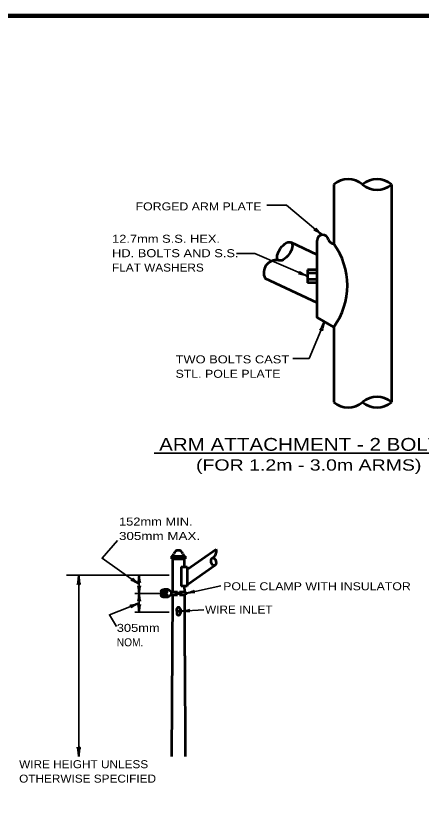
# Model space of a CAD drawing. Extents: x -23 to 690, y -228 to 443.
# Drawn here: x 229.5 to 356, y 192.8 to 437.8 of the extents above; entities that cross this region are included whole.
import ezdxf
from ezdxf.enums import TextEntityAlignment as Align

# ---------------------------------------------------------------- set-up
doc = ezdxf.new("R2010")
doc.units = 0
doc.layers.add('1', color=7, linetype='Continuous', lineweight=35)

msp = doc.modelspace()

# ---------------------------------------------------------------- hatches: boundary and pattern name
at = {"layer": '1'}
h = msp.add_hatch(color=256, dxfattribs=at)
edge = h.paths.add_edge_path()
edge.add_ellipse((275.808, 258.088), major_axis=(0.907, 0), ratio=0.6666667, start_angle=0, end_angle=360)
h = msp.add_hatch(color=256, dxfattribs=at)
edge = h.paths.add_edge_path()
edge.add_ellipse((275.808, 256.835), major_axis=(0.907, 0), ratio=0.6666667, start_angle=0, end_angle=360)

# ---------------------------------------------------------------- linework, layer by layer
at = {"layer": '1', "lineweight": 53}
for p, q in [((328.678, 385.1), (328.678, 366.6)), ((346.678, 385.1), (346.678, 317.1)), ((323.561, 363.183), (315.404, 366.986)), ((323.482, 358.445), (320.482, 358.445)), ((320.482, 358.445), (320.482, 354.445)), ((323.561, 348.183), (307.247, 355.79)), ((323.482, 357.445), (320.482, 357.445)), ((323.482, 355.445), (320.482, 355.445)), ((323.482, 354.445), (320.482, 354.445)), ((328.678, 340.6), (328.678, 317.1)), ((283.035, 265.061), (291.955, 271.301)), ((278.1, 269.095), (282.32, 269.095)), ((278.1, 269.095), (278.1, 268.195)), ((278.1, 268.195), (282.32, 268.195)), ((278.4, 268.195), (278.34, 257.915)), ((282.02, 268.195), (282.04, 265.775)), ((282.32, 269.095), (282.32, 268.195)), ((281.11, 265.775), (283.01, 265.775)), ((281.11, 265.775), (281.11, 259.735)), ((283.01, 265.775), (283.01, 259.735)), ((283.035, 260.221), (291.475, 266.121)), ((283.01, 259.735), (281.11, 259.735)), ((282.06, 259.735), (282.08, 257.915)), ((277.02, 258.695), (275.8, 258.695)), ((277.94, 257.915), (277.02, 258.695)), ((277.94, 257.915), (279.92, 257.915)), ((277.94, 257.915), (277.94, 257.015)), ((279.42, 257.915), (279.42, 257.015)), ((279.92, 257.915), (279.92, 257.015)), ((280.52, 257.915), (282.48, 257.915)), ((280.52, 257.915), (280.52, 257.015)), ((281, 257.915), (281, 257.015)), ((282.48, 257.915), (282.48, 257.015)), ((277.02, 256.235), (275.8, 256.235)), ((277.94, 257.015), (277.02, 256.235)), ((277.94, 257.015), (279.92, 257.015)), ((278.34, 257.015), (278.1, 206.515)), ((280.52, 257.015), (282.48, 257.015)), ((282.08, 257.015), (282.168, 237.955)), ((279.68, 252.455), (279.7, 251.255)), ((280.9, 252.475), (280.9, 251.255)), ((282.18, 237.955), (282.32, 206.515))]:
    msp.add_line(p, q, dxfattribs=at)
at = {"layer": '1'}
for p, q in [((272.629, 301.175), (367.649, 301.175)), ((245.329, 263.089), (277.329, 263.089)), ((249.145, 263.089), (249.145, 206.515)), ((267.971, 257.404), (267.971, 263.089)), ((282.509, 257.449), (293.413, 259.808)), ((266.657, 257.404), (274.657, 257.404)), ((267.971, 257.404), (267.971, 251.593)), ((280.94, 251.88), (288.21, 252.352)), ((266.657, 251.593), (277.329, 251.593))]:
    msp.add_line(p, q, dxfattribs=at)
at = {"layer": '1', "lineweight": 158}
msp.add_lwpolyline([(684.026, 437.805), (24.276, 437.722), (24.36, -0.611)], dxfattribs=at)
at = {"layer": '1'}
for points in [[(325.01, 369.374), (313.992, 378.629), (307.832, 378.629)], [(320.482, 356.445), (304.054, 363.511), (298.304, 363.511)], [(325.826, 342.247), (320.974, 330.729), (315.963, 330.729)], [(268.019, 260.256), (256.395, 268.416), (261.221, 273.923)], [(267.951, 254.408), (258.706, 250.804), (260.882, 247.133)]]:
    msp.add_lwpolyline(points, dxfattribs=at)
at = {"layer": '1', "lineweight": 53}
msp.add_lwpolyline([(328.678, 340.6), (323.482, 343.6), (323.482, 367.6)], dxfattribs=at)
for centre, radius, start, end in [((333.178, 379.861), 6.907, 49.34186, 130.65814), ((342.178, 379.861), 6.907, 49.34186, 130.65814), ((342.178, 390.332), 6.907, 229.34186, 310.65814), ((325.269, 367.606), 1.787, 7.93348, 180.19616), ((328.793, 368.449), 1.852, 198.77174, 266.46102), ((310.949, 353.6), 21.985, 323.74899, 36.25101), ((310.874, 357.511), 4.015, 82.46091, 205.39139), ((342.178, 311.869), 6.907, 49.34186, 130.65814), ((333.178, 322.34), 6.907, 229.34186, 310.65814), ((342.178, 322.34), 6.907, 229.34186, 310.65814), ((277.902, 270.019), 0.936, 281.94387, 347.91984), ((280.213, 269.418), 1.453, 16.19781, 163.80219), ((282.523, 270.019), 0.936, 192.08016, 258.05613), ((289.835, 270.525), 2.264, 295.32486, 20.09191), ((280.289, 252.478), 0.605, 358.85054, 181.71286), ((280.295, 251.269), 0.605, 358.85054, 181.71286), ((280.295, 251.232), 0.605, 178.28714, 1.14946)]:
    msp.add_arc(centre, radius, start, end, dxfattribs=at)
at = {"layer": '1', "lineweight": 40}
for centre, major_axis, ratio, start_param, end_param in [((323.997, 369.865), (1.468, -1.029), 0.122415, 0.8963533, 3.1415927), ((323.997, 369.865), (1.468, -1.029), 0.122415, 0.8963533, 3.1415927), ((324.288, 370.257), (-1.232, 1.264), 0.07063, 6.2823074, 8.5597026), ((324.288, 370.257), (-1.232, 1.264), 0.07063, 6.2823074, 8.5597026), ((319.536, 357.082), (1.544, -0.855), 0.07063, 3.1407148, 5.41811), ((319.536, 357.082), (1.544, -0.855), 0.07063, 3.1407148, 5.41811), ((319.371, 356.622), (1.702, -0.562), 0.122415, 0.8963533, 3.1415927), ((319.371, 356.622), (1.702, -0.562), 0.122415, 0.8963533, 3.1415927), ((325.196, 341.297), (-0.844, -1.55), 0.07063, 6.2823074, 8.5597026), ((325.196, 341.297), (-0.844, -1.55), 0.07063, 6.2823074, 8.5597026), ((325.657, 341.134), (0.549, 1.706), 0.122415, 0.8963533, 3.1415927), ((325.657, 341.134), (0.549, 1.706), 0.122415, 0.8963533, 3.1415927), ((248.933, 261.968), (0.176, 1.756), 0.07063, 3.1407148, 5.41811), ((249.421, 261.998), (-0.156, 1.786), 0.122415, 0.8963533, 3.1415927), ((267.223, 261.073), (-1.337, 1.153), 0.07063, 6.2823074, 8.5597026), ((267.223, 261.073), (-1.337, 1.153), 0.07063, 6.2823074, 8.5597026), ((267.763, 261.959), (0.176, 1.756), 0.07063, 4.6265008, 5.41811), ((268.251, 261.989), (-0.156, 1.786), 0.122415, 0.8963533, 1.6612166), ((266.967, 260.657), (1.551, -0.898), 0.122415, 0.8963533, 3.1415927), ((266.967, 260.657), (1.551, -0.898), 0.122415, 0.8963533, 3.1415927), ((267.82, 262.451), (0.176, 1.756), 0.07063, 3.1407148, 4.3375003), ((267.82, 258.043), (0.176, -1.756), 0.07063, 1.9456851, 3.1424706), ((268.191, 262.498), (-0.156, 1.786), 0.122415, 1.9568509, 3.1415927), ((268.191, 257.995), (-0.156, -1.786), 0.122415, 3.1415927, 4.3263344), ((267.763, 258.534), (0.176, -1.756), 0.07063, 0.8650754, 1.6566845), ((267.763, 256.275), (0.176, 1.756), 0.07063, 4.6265008, 5.41811), ((268.251, 258.505), (-0.156, -1.786), 0.122415, 4.6219687, 5.386832), ((268.251, 256.304), (-0.156, 1.786), 0.122415, 0.8963533, 1.6612166), ((283.517, 257.95), (-1.712, -0.53), 0.122415, 0.8963533, 3.1415927), ((283.517, 257.95), (-1.712, -0.53), 0.122415, 0.8963533, 3.1415927), ((283.649, 257.479), (1.754, 0.2), 0.07063, 6.2823074, 8.5597026), ((283.649, 257.479), (1.754, 0.2), 0.07063, 6.2823074, 8.5597026), ((267.82, 256.766), (0.176, 1.756), 0.07063, 3.1407148, 4.3375003), ((268.191, 256.814), (-0.156, 1.786), 0.122415, 1.9568509, 3.1415927), ((266.83, 254.199), (-1.7, -0.474), 0.07063, 6.2823074, 8.5597026), ((267.035, 253.755), (1.607, 0.794), 0.122415, 0.8963533, 3.1415927), ((267.82, 252.231), (0.176, -1.756), 0.07063, 1.9456851, 3.1424706), ((267.763, 252.723), (0.176, -1.756), 0.07063, 0.8650754, 1.6566845), ((268.251, 252.693), (-0.156, -1.786), 0.122415, 4.6219687, 5.386832), ((268.191, 252.184), (-0.156, -1.786), 0.122415, 3.1415927, 4.3263344), ((282.01, 252.227), (-1.772, -0.272), 0.122415, 0.8963533, 3.1415927), ((282.071, 251.742), (-1.764, 0.061), 0.07063, 3.1407148, 5.41811), ((248.869, 207.606), (0.156, -1.786), 0.122415, 0.8963533, 3.1415927), ((248.869, 207.606), (0.156, -1.786), 0.122415, 0.8963533, 3.1415927), ((249.357, 207.636), (-0.176, -1.756), 0.07063, 3.1407148, 5.41811), ((249.357, 207.636), (-0.176, -1.756), 0.07063, 3.1407148, 5.41811)]:
    msp.add_ellipse(centre, major_axis=major_axis, ratio=ratio, start_param=start_param, end_param=end_param, dxfattribs=at)
at = {"layer": '1', "lineweight": 53}
for centre, major_axis, ratio in [((313.402, 364.239), (-2.002, -2.748), 0.476726), ((291.195, 267.314), (-0.27, 1.196), 0.618585), ((275.808, 258.088), (0.907, 0), 0.666667), ((275.808, 256.835), (0.907, 0), 0.666667)]:
    msp.add_ellipse(centre, major_axis=major_axis, ratio=ratio, dxfattribs=at)

# ---------------------------------------------------------------- texts
at = {"layer": '1'}
for s, height, width, p in [('FORGED ARM PLATE', 2.5, 1.15, (266.864, 377.017)), ('12.7mm S.S. HEX.', 2.5, 1.2, (259.535, 366.912)), ('HD. BOLTS AND S.S.', 2.5, 1.2, (259.535, 362.412)), ('FLAT WASHERS', 2.5, 1.1, (259.535, 357.912)), ('TWO BOLTS CAST', 2.5, 1.2, (279.348, 329.262)), ('STL. POLE PLATE', 2.5, 1.15, (279.348, 324.762)), ('(FOR 1.2m - 3.0m ARMS)', 3.5, 1.3, (285.715, 295.789)), ('152mm MIN.', 2.5, 1.2, (261.697, 278.623)), ('305mm MAX.', 2.5, 1.25, (261.697, 274.123)), ('POLE CLAMP WITH INSULATOR', 2.5, 1.15, (294.189, 258.42)), ('WIRE INLET', 2.5, 1.1, (288.547, 251.144)), ('305mm', 2.5, 1.2, (261.005, 245.433)), ('NOM.', 2.5, 0.95, (261.005, 240.933)), ('WIRE HEIGHT UNLESS', 2.5, 1.1, (230.548, 202.869)), ('OTHERWISE SPECIFIED', 2.5, 1.1, (230.548, 198.369))]:
    msp.add_text(s, height=height, dxfattribs=dict(at, width=width)).set_placement(p)
at = {"layer": '1', "width": 1.2}
msp.add_text('ARM ATTACHMENT - 2 BOLTS', height=4, dxfattribs=at).set_placement((320.218, 301.968), align=Align.CENTER)

doc.saveas('drawing.dxf')
